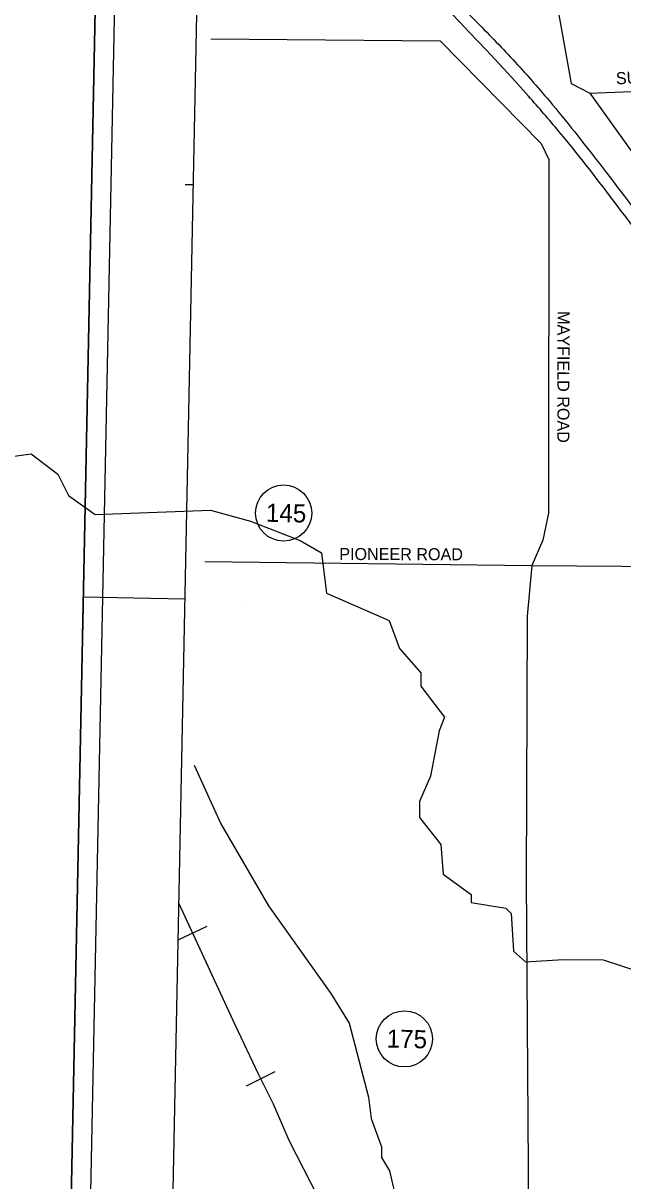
# Model space of a CAD drawing. Extents: x 331323 to 388339, y 121519 to 205315.
# Drawn here: x 354113 to 357842, y 128453 to 135654 of the extents above; entities that cross this region are included whole.
import ezdxf

# ---------------------------------------------------------------- set-up
doc = ezdxf.new("R2010")
doc.units = 0
for name, color, linetype in [('CA-TEXT', 7, 'Continuous'), ('Level 1', 7, 'Continuous'), ('Level 2', 7, 'Continuous'), ('Level 4', 7, 'Continuous'), ('Level 5', 7, 'Continuous'), ('Level 57', 7, 'Continuous'), ('P_RDWY_Text', 7, 'Continuous'), ('PLT_Sheet_Border', 7, 'Continuous'), ('PLT_Sheet_Info', 7, 'Continuous')]:
    doc.layers.add(name, color=color, linetype=linetype)

msp = doc.modelspace()

# ---------------------------------------------------------------- linework, layer by layer
at = {"layer": 'CA-TEXT'}
for p, q in [((355732.6, 132606.8), (355732.6, 132606.8)), ((356483.7, 129335.8), (356483.7, 129335.8))]:
    msp.add_line(p, q, dxfattribs=at)
for centre in [(355732.6, 132606.8), (356483.7, 129335.8)]:
    msp.add_circle(centre, 174.7, dxfattribs=at)
at = {"layer": 'Level 1'}
msp.add_lwpolyline([(356203.5, 127771.7), (356045.3, 128142.2), (355947.1, 128351.4), (355766.9, 128703.1), (355668.9, 128929), (355578.9, 129113.1), (355431.6, 129422.8), (355081.1, 130179.4)], dxfattribs=at)
at = {"layer": 'Level 2'}
msp.add_lwpolyline([(355175.6, 131038.6), (355343.1, 130673.6), (355638.6, 130162.6), (356025.5, 129617.4), (356140.6, 129433), (356261.5, 128973.6), (356276.9, 128840.1), (356342, 128664.5), (356341.4, 128597.9), (356390.6, 128514.1), (356422.8, 128380.5), (356472, 128296.7), (356635.7, 127953.5), (356726, 127802.7), (356775.1, 127693.9), (356925.3, 127468.4)], dxfattribs=at)
for points in [[(360974.7, 130246.3), (359488.5, 132249.8), (358879.2, 133079.6), (357889.3, 134411.1), (357444.5, 134981.1), (357256, 135199.5), (355476.6, 136957.3)], [(355623.7, 136961.1), (356920.4, 135674.4), (357158.4, 135427.5), (357273.3, 135300.2), (357385.4, 135170.3), (357696.2, 134781.1), (358305.3, 133973.7), (358998.6, 133039.4), (360249.6, 131353.3), (361069.7, 130244.3)]]:
    msp.add_spline(points, degree=3, dxfattribs=at)
at = {"layer": 'Level 4'}
for points in [[(357409.6, 135905.1), (357520.6, 135279.1), (357636.8, 135219.7)], [(355281, 135557.7), (356705.7, 135544.8), (357333.7, 134905.7), (357382.8, 134805.3), (357379.2, 132605.3), (357344.3, 132438.9), (357276.1, 132281.2)], [(357636.8, 135219.7), (358521.1, 135253.3)], [(357636.8, 135219.7), (358007.3, 134699.6), (358427.8, 134170.8), (358592.7, 133969.3), (358867, 133875.2), (359391.2, 133737.1), (359722.9, 133534.1), (359929.5, 133323.9), (360010.9, 133106.4), (360037.1, 132339.5), (360103.2, 132272.3), (361293.2, 132269.2)], [(357276.1, 132281.2), (357836.2, 132275.7), (358185.5, 132264.5), (358432.9, 132319.9), (358626.9, 132391.1), (358925.1, 132531.9), (359524.4, 132867.8), (360005.5, 133125.7), (360280.5, 133253.6), (360592.2, 133324.2), (360879.8, 133342.2), (362050, 133332.6), (362656.9, 133328.3)], [(355241.8, 132306.1), (357276.1, 132281.2)], [(357276.1, 132281.2), (357248.1, 131964.8), (357241, 130321.4)], [(357241, 130321.4), (357255.5, 128239.6), (357248.4, 127474.7)]]:
    msp.add_lwpolyline(points, dxfattribs=at)
at = {"layer": 'Level 5'}
for p, q in [((355076.2, 129952.2), (355257.6, 130036.2)), ((355501.1, 129044.6), (355680.7, 129132.5))]:
    msp.add_line(p, q, dxfattribs=at)
msp.add_lwpolyline([(356390, 127470.7), (356331.8, 127564.6), (356203.5, 127771.7), (356045.3, 128142.2), (355947.1, 128351.4), (355766.9, 128703.1), (355668.9, 128929), (355578.9, 129113.1), (355431.6, 129422.8), (355136.3, 130060.3)], dxfattribs=at)
at = {"layer": 'Level 57'}
for points in [[(353887.8, 132936.9), (354163.4, 132976), (354329, 132849.5), (354394.5, 132715.6), (354560.2, 132597.4), (355277.7, 132624.3), (355527.2, 132555.4), (355834.7, 132435.9), (355967.4, 132359.7), (355998.5, 132109.4), (356388.9, 131939.2), (356454, 131763.6), (356586, 131612.4), (356585.3, 131529.1), (356733.6, 131336.1), (356699.5, 131253), (356646.8, 130970.2), (356578.7, 130812.5), (356577.7, 130712.5), (356709.6, 130544.6), (356724.6, 130361.1), (356898.6, 130234.5), (356898.1, 130184.5)], [(356898.1, 130184.5), (357114.6, 130149.2), (357147.7, 130115.6), (357162.2, 129882.1), (357236.6, 129814.8), (357470.3, 129829.4), (357720.5, 129827.1), (358061.4, 129715.7), (358317.1, 129413.3), (358466.5, 129328.7), (358907.9, 129266.3), (359023.9, 129181.9), (359257.5, 129196.5), (359783.1, 129208.4), (361567.8, 129208.9)]]:
    msp.add_lwpolyline(points, dxfattribs=at)
at = {"layer": 'P_RDWY_Text'}
msp.add_lwpolyline([(354597.6, 137585.1), (371594.2, 137242.8), (371372.7, 126245), (354376.1, 126587.3)], close=True, dxfattribs=at)
at = {"layer": 'PLT_Sheet_Border'}
for points in [[(354376.1, 126587.3), (371372.7, 126245), (371594.2, 137242.8), (354597.6, 137585.1)], [(354501.1, 126834.8), (371047.8, 126501.6), (371259.2, 136999.5), (354712.6, 137332.7)]]:
    msp.add_lwpolyline(points, close=True, dxfattribs=at)
at = {"layer": 'PLT_Sheet_Info'}
for p, q in [((355018.6, 127074.5), (355219.9, 137072.4)), ((355171.1, 134647.9), (355121.1, 134648.9)), ((354481.9, 131836.2), (354491.9, 132336.1)), ((354486.9, 132086.2), (355119.3, 132073.4)), ((355494.2, 132065.9), (355494.2, 132065.9))]:
    msp.add_line(p, q, dxfattribs=at)

# ---------------------------------------------------------------- texts
at = {"layer": 'CA-TEXT'}
for s, height, rotation, p in [('SUNSET GRAZE', 75, 2.17988, (357800.3, 135273.7)), ('MAYFIELD ROAD', 75, 269.90555, (357436.1, 133862.8)), ('145', 112.5, 358.76698, (355621.6, 132552.9)), ('PIONEER ROAD', 75, 359.8543, (356078.8, 132314.7)), ('175', 112.5, 358.76698, (356372.7, 129281.9))]:
    msp.add_text(s, height=height, rotation=rotation, dxfattribs=at).set_placement(p)

doc.saveas('drawing.dxf')
